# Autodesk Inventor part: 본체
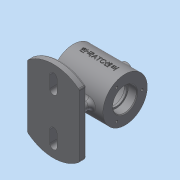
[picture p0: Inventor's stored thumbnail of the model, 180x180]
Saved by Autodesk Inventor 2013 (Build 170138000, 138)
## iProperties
Created: 2017-12
Part Number: 본체
Material: 일반
Document SubType Name: Modeling
Designer: dgall
Density: 1 g/cm^3
Author: dgall
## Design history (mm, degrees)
sketch "스케치1"
  geometry: L1 (0, 0)-(70, 0); L2 (12, 16)-(0, 16); L3 (0, 16)-(0, 30); L4 (0, 30)-(70, 30); L5 (70, 30)-(70, 16); L6 (70, 16)-(58, 16); L7 (58, 16)-(58, 14); L8 (58, 14)-(55, 14); L9 (55, 14)-(55, 25); L10 (55, 25)-(15, 25); L11 (15, 25)-(15, 14); L12 (15, 14)-(12, 14); L13 (12, 16)-(12, 14)
  constraints: 26 end point, 9 parallel, 2 perpendicular, 2 vertical alignment, 1 collinear, 1 horizontal
  dimensions: "d0" = 70 distance of L3.end L4.end; "d2" = 60 diameter of L4 L1; "d3" = 32 diameter of L2 L1; "d4" = 28 diameter of L12 L1; "d5" = 50 diameter of L10 L1; "d6" = 28 diameter of L8 L1; "d7" = 32 diameter of L6 L1; "d8" = 12 distance of L2.start L2.end; "d9" = 12 distance of L5.end L6.end; "d10" = 40 distance of L9.end L10.end; "d11" = 3 distance of L11.end L12.end
revolve "회전1" sketch "스케치1" stored, may be unused: angle "d12" = 90 deg
node "작업 평면1"
sketch "스케치2"
  geometry: L1 (0, 30)-(0, -30) reference; C1 r 8 at (-35, 0); 1 further point
  constraints: 1 centre point, 1 horizontal alignment
  dimensions: "d14" = 16 diameter of C1; "d15" = 35 distance from line of L1 C1.centre
extrude "돌출1" join sketch "스케치2" stored distance "d16" = 10; taper "d17" = 0 deg
hole "구멍1" diameter "d20" = 8; stored, may be unused: countersink angle "d24" = 90 deg, drill point angle "d26" = 118 deg; dims "d18" = 10, "d19" = 10, "d21" = 6, "d22" = 4, "d23" = 2, "d25" = 8
sketch "스케치3"
  geometry: C1 r 30 at (0, 0) reference; 1 further point
  constraints: 1 vertical alignment
  dimensions: "d27" = 23 distance of C1.centre point (0, 23)
hole "구멍2" sketch "스케치3" at (0, 23) diameter "d28" = 3.242; stored, may be unused: countersink angle "d32" = 90 deg, drill point angle "d34" = 118 deg; dims "d29" = 8, "d30" = 4, "d31" = 2, "d33" = 10
sketch "스케치4"
  geometry: C1 r 16 at (0, 0) reference; 1 further point
  constraints: 1 vertical alignment
  dimensions: "d38" = 23 distance of C1.centre point (0, 23)
hole "구멍3" sketch "스케치4" at (0, 23) diameter "d39" = 3.242; stored, may be unused: countersink angle "d43" = 90 deg, drill point angle "d45" = 118 deg; dims "d40" = 8, "d41" = 4, "d42" = 2, "d44" = 10
node "작업 평면2"
sketch "스케치5"
  geometry: L1 (0, 30)-(0, -30) reference; L2 (-70, -42.426)-(-70, 42.426); L3 (0, -42.426)-(0, 42.426); L4 (-40, -24)-(-40, -40); L5 (-30, -40)-(-30, -24); L6 (-30, 24)-(-30, 40); L7 (-40, 40)-(-40, 24); A1 r 55 centre (-35, 0) between (-70, -42.426) and (-70, 42.426); A2 r 55 centre (-35, 0) between (-70, -42.426) and (0, -42.426); A3 r 55 centre (-35, 0) between (0, 42.426) and (-70, 42.426); A4 r 5 centre (-35, -40) between (-40, -40) and (-30, -40); A5 r 5 centre (-35, -24) between (-30, -24) and (-40, -24); A6 r 5 centre (-35, 40) between (-30, 40) and (-40, 40); A7 r 5 centre (-35, 24) between (-40, 24) and (-30, 24); 1 further point
  constraints: 16 point on circle, 13 end point, 8 tangent, 7 centre point, 4 parallel, 3 vertical alignment, 2 collinear, 2 concentric, 1 horizontal alignment
  dimensions: "d50" = 110 diameter of A1; "d52" = 35 distance from line of L1 A1.centre; "d53" = 70 distance between parallel lines of L3 L2; "d54" = 5 radius of A4; "d55" = 5 radius of A7; "d56" = 16 distance of A5.centre A4.centre; "d57" = 16 distance of A6.centre A7.centre; "d58" = 24 distance of A1.centre A5.centre; "d59" = 24 distance of A1.centre A7.centre
extrude "돌출2" join sketch "스케치5" distance "d60" = 10; taper "d61" = 0 deg
sketch "스케치6"
  geometry: L1 (0, 42.426)-(0, -42.426) reference; L2 (20, 5)-(50, 5); L3 (50, -5)-(20, -5); A1 r 5 centre (35, 24) between (30, 24) and (40, 24) reference; A2 r 55 centre (35, 0) between (0, -42.426) and (70, -42.426) reference; A3 r 5 centre (50, 0) between (50, -5) and (50, 5); A4 r 5 centre (20, 0) between (20, 5) and (20, -5); 2 further points
  constraints: 4 end point, 4 point on circle, 4 tangent, 2 centre point, 1 horizontal alignment, 1 midpoint, 1 parallel, 1 perpendicular, 1 vertical alignment
  dimensions: "d62" = 5 radius of A3; "d64" = 30 distance of A3.centre A4.centre
extrude "돌출3" join sketch "스케치6" stored distance "d65" = 10; taper "d66" = 0 deg
node "작업 평면3"
sketch "스케치7"
  geometry: L1 (-35, 30)-(35, 30) reference; 2 further points
  constraints: 1 horizontal alignment, 1 other
  dimensions: "d67" = 35 distance of point (0, 0) point (-35, 0)
feature "엠보싱1" sketch "스케치7" dims "d68" = 0.5, "d69" = 0
chamfer "모따기1" distance "d70" = 1; stored, may be unused: second distance "d71" = 2, angle "d72" = 45 deg
fillet "모깎기1" dims "d73" = 0.3
fillet "모깎기2" dims "d74" = 3
fillet "모깎기3" dims "d75" = 3
fillet "모깎기4" dims "d76" = 3
fillet "모깎기5" dims "d77" = 5
fillet "모깎기6" dims "d78" = 3
node "솔리드1"
pattern_circular "원형 패턴1" dims angle "d36" = 360 deg
pattern_circular "원형 패턴2" dims angle "d47" = 360 deg
other parameters: "d13" = 37, "d49" = -62
